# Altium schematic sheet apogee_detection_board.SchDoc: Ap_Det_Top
size Letter; Revision: 1.2; SheetNumber: 1; SheetTotal: 2
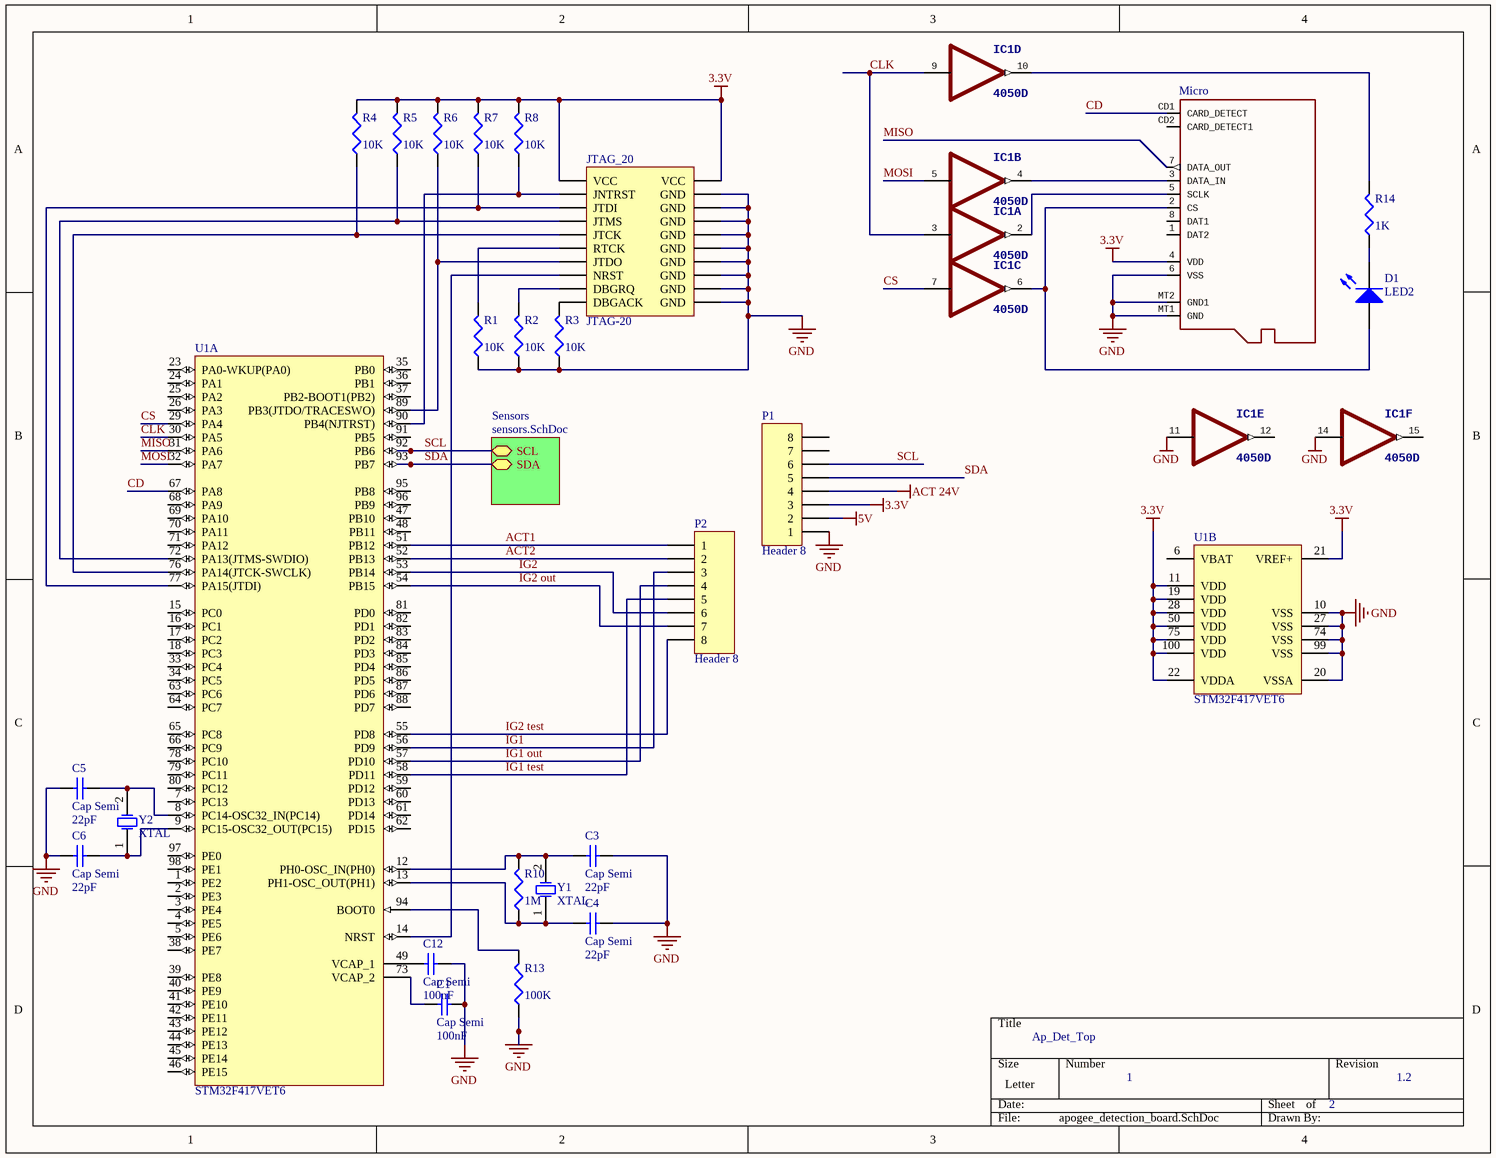
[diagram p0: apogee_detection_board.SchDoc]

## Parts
C1  Cap Semi  value 100nF  [C1206]
C3  Cap Semi  value 22pF  [C1206]
C4  Cap Semi  value 22pF  [C1206]
C5  Cap Semi  value 22pF  [C1206]
C6  Cap Semi  value 22pF  [C1206]
C12  Cap Semi  value 100nF  [C1206]
D1  LED2  [3.2X1.6X1.1]
IC1  4050D  [SO16]  (parts A,B,C,D,E,F of 7)
JTAG_20  JTAG-20  [PCBComponent_1]
Micro  (no value)  [MICROSD]
P1  Header 8  [HDR1X8]
P2  Header 8  [HDR1X8]
R1  value 10K  [J1-0603]  (hidden comment: RTCK PD)
R2  value 10K  [J1-0603]  (hidden comment: DBGRQ PD)
R3  value 10K  [J1-0603]  (hidden comment: DBGACK PD)
R4  value 10K  [J1-0603]  (hidden comment: RTCK PD)
R5  value 10K  [J1-0603]  (hidden comment: RTCK PD)
R6  value 10K  [J1-0603]  (hidden comment: RTCK PD)
R7  value 10K  [J1-0603]  (hidden comment: RTCK PD)
R8  value 10K  [J1-0603]  (hidden comment: RTCK PD)
R10  value 1M  [J1-0603]  (hidden comment: RTCK PD)
R13  value 100K  [J1-0603]  (hidden comment: RTCK PD)
R14  value 1K  [J1-0603]  (hidden comment: DBGRQ PD)
U1  STM32F417VET6  [STM-LQFP100_N]  (parts A,B of 2)
Y1  XTAL  [R38]
Y2  XTAL  [R38]

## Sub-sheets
Sensors = sensors.SchDoc: SCL (bidir), SDA (bidir)

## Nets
3.3V: JTAG_20.1(VCC) JTAG_20.2(VCC) Micro.4(VDD) P1.3 R4.2 R5.2 R6.2 R7.2 R8.2 U1.11(VDD) U1.19(VDD) U1.21(VREF+) U1.22(VDDA) U1.28(VDD) U1.50(VDD) U1.75(VDD) U1.100(VDD)
5V: P1.2
ACT 24V: P1.4
GND: C1.2 C3.1 C4.1 C5.1 C6.1 C12.2 IC1.11(I) IC1.14(I) JTAG_20.4(GND) JTAG_20.6(GND) JTAG_20.8(GND) JTAG_20.10(GND) JTAG_20.12(GND) JTAG_20.14(GND) JTAG_20.16(GND) JTAG_20.18(GND) JTAG_20.20(GND) Micro.6(VSS) Micro.MT1(GND) Micro.MT2(GND1) P1.1 R1.1 R2.1 R3.1 R13.1 U1.10(VSS) U1.20(VSSA) U1.27(VSS) U1.74(VSS) U1.99(VSS)
ACT1: P2.1 U1.51(PB12)
ACT2: P2.2 U1.52(PB13)
CD: Micro.CD1(CARD_DETECT) U1.67(PA8)
CLK: IC1.3(I) IC1.9(I) U1.30(PA5)
CS: IC1.7(I) U1.29(PA4)
IG1: P2.3 U1.56(PD9)
IG1 out: P2.4 U1.57(PD10)
IG1 test: P2.5 U1.58(PD11)
IG2: P2.6 U1.53(PB14)
IG2 out: P2.7 U1.54(PB15)
IG2 test: P2.8 U1.55(PD8)
MISO: Micro.7(DATA_OUT) U1.31(PA6)
MOSI: IC1.5(I) U1.32(PA7)
SCL: P1.6 U1.92(PB6) ; sheet Sensors/SCL
SDA: P1.5 U1.93(PB7) ; sheet Sensors/SDA
NetC1_1: C1.1 U1.73(VCAP_2)
NetC3_2: C3.2 R10.2 U1.12(PH0-OSC_IN(PH0)) Y1.2(OSC2)
NetC4_2: C4.2 R10.1 U1.13(PH1-OSC_OUT(PH1)) Y1.1(OSC1)
NetC5_2: C5.2 U1.8(PC14-OSC32_IN(PC14)) Y2.2(OSC2)
NetC6_2: C6.2 U1.9(PC15-OSC32_OUT(PC15)) Y2.1(OSC1)
NetC12_1: C12.1 U1.49(VCAP_1)
NetD1_1: D1.1(A) IC1.6(O) Micro.2(CS)
NetD1_2: D1.2(K) R14.1
NetIC1_2: IC1.2(O) Micro.5(SCLK)
NetIC1_4: IC1.4(O) Micro.3(DATA_IN)
NetIC1_10: IC1.10(O) R14.2
NetJTAG_20_3: JTAG_20.3(JNTRST) R8.1 U1.90(PB4(NJTRST))
NetJTAG_20_5: JTAG_20.5(JTDI) R7.1 U1.77(PA15(JTDI))
NetJTAG_20_7: JTAG_20.7(JTMS) R5.1 U1.72(PA13(JTMS-SWDIO))
NetJTAG_20_9: JTAG_20.9(JTCK) R4.1 U1.76(PA14(JTCK-SWCLK))
NetJTAG_20_11: JTAG_20.11(RTCK) R1.2
NetJTAG_20_13: JTAG_20.13(JTDO) R6.1 U1.89(PB3(JTDO/TRACESWO))
NetJTAG_20_15: JTAG_20.15(NRST) U1.14(NRST)
NetJTAG_20_17: JTAG_20.17(DBGRQ) R2.2
NetJTAG_20_19: JTAG_20.19(DBGACK) R3.2
NetR13_2: R13.2 U1.94(BOOT0)

Not connected (* = marked no-connect by the designer): IC1 12(O) 15(O); Micro 1(DAT2) 8(DAT1) CD2(CARD_DETECT1); P1 7 8; U1 1(PE2) 2(PE3) 3(PE4) 4(PE5) 5(PE6) 6(VBAT) 7(PC13) 15(PC0) 16(PC1) 17(PC2) 18(PC3) 23(PA0-WKUP(PA0)) 24(PA1) 25(PA2) 26(PA3) 33(PC4) 34(PC5) 35(PB0) 36(PB1) 37(PB2-BOOT1(PB2)) 38(PE7) 39(PE8) 40(PE9) 41(PE10) 42(PE11) 43(PE12) 44(PE13) 45(PE14) 46(PE15) 47(PB10) 48(PB11) 59(PD12) 60(PD13) 61(PD14) 62(PD15) 63(PC6) 64(PC7) 65(PC8) 66(PC9) 68(PA9) 69(PA10) 70(PA11) 71(PA12) 78(PC10) 79(PC11) 80(PC12) 81(PD0) 82(PD1) 83(PD2) 84(PD3) 85(PD4) 86(PD5) 87(PD6) 88(PD7) 91(PB5) 95(PB8) 96(PB9) 97(PE0) 98(PE1)

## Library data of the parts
C1 C3-C6 C12 = Cap Semi: Capacitor (Semiconductor SIM Model)
D1 = LED2: Typical RED, GREEN, YELLOW, AMBER GaAs LED
IC1 = 4050D: Hex non-inverting BUFFER
JTAG_20 = HEADER 10X2: 20-pin JTAG header
Micro = MICROSD
P1 P2 = Header 8: Header, 8-Pin
R1-R8 R10 R13 R14 = Res3: Resistor
U1 = STM32F417VET6: ARM Cortex-M4 32-bit MCU+FPU, 210 DMIPS, 512 kB Flash, 192 kB Internal RAM, 82 I/Os, 100-pin LQFP, -40 to 85 degC, Tray; Manufacturer: STMicroelectronics; D/A Converter: 2x12-bit; FLASH Size (Prog) (kB): 512; I/Os (High Current): 82; Internal RAM Size (kB): 192; Operating Frequency(F) (Processor speed) (MHz): 168; Supply Voltage(Vcc) max (V): 3.6; Supply Voltage(Vcc) min (V): 1.8
Y1 Y2 = XTAL: Crystal Oscillator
